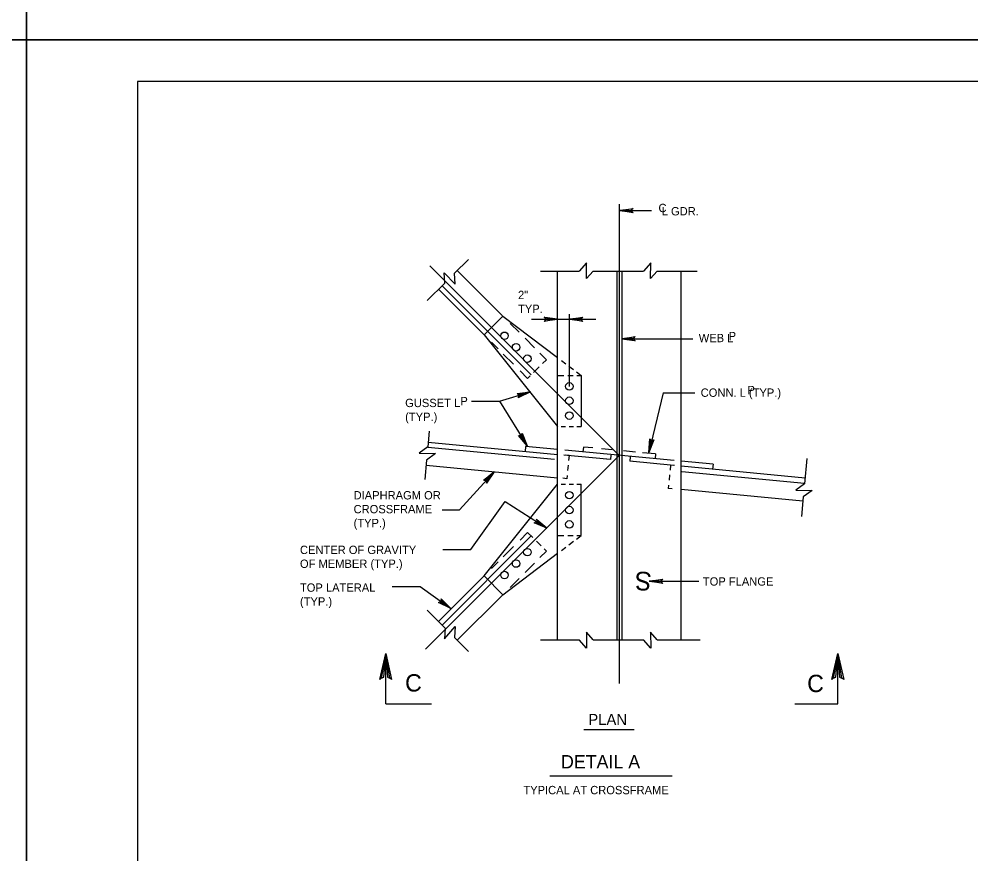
# Model space of a CAD drawing. Extents: x 30 to 2621, y -33 to 1155.
# Drawn here: x 868.8 to 1211.9, y 267.8 to 568.5 of the extents above; entities that cross this region are included whole.
import ezdxf

# ---------------------------------------------------------------- set-up
doc = ezdxf.new("R2010")
doc.units = 0
doc.layers.add('1', color=7, linetype='Continuous')
doc.layers.add('PLT-BNDY', color=7, linetype='Continuous')

msp = doc.modelspace()

# ---------------------------------------------------------------- linework, layer by layer
at = {"layer": '1'}
for p, q in [((911.5, 546), (911.5, -18)), ((1697.5, 546), (911.5, 546)), ((1085.19, 492.79), (1085.19, 501.85)), ((1085.27, 499.48), (1096.72, 499.48)), ((1085.19, 329.19), (1085.19, 492.79)), ((1025.81, 476.94), (1030.8, 481.93)), ((1016.93, 479.55), (1085.16, 411.31)), ((1026.79, 477.91), (1043.06, 461.64)), ((1056.82, 477.74), (1070.77, 477.74)), ((1062.9, 344.89), (1062.9, 477.74)), ((1075.75, 477.74), (1093.87, 477.74)), ((1084.24, 477.74), (1084.24, 344.89)), ((1086.07, 477.74), (1086.07, 344.89)), ((1098.85, 477.74), (1113.22, 477.74)), ((1107.42, 344.89), (1107.42, 477.74)), ((1015.95, 467.08), (1022.29, 473.41)), ((1020.03, 471.15), (1036.47, 454.71)), ((1021.32, 472.45), (1053.43, 440.34)), ((1036.47, 454.71), (1043.23, 461.47)), ((1043.23, 461.47), (1062.9, 446.58)), ((1053.54, 460.36), (1067.17, 460.36)), ((1067.17, 436.17), (1067.17, 462.24)), ((1067.17, 460.36), (1076.68, 460.36)), ((1045.83, 458.86), (1049.04, 455.66)), ((1036.47, 454.71), (1062.9, 421.7)), ((1051.19, 453.5), (1054.59, 450.11)), ((1086.07, 453.33), (1111.7, 453.33)), ((1039.07, 452.1), (1041.51, 449.67)), ((1043.35, 447.83), (1047.04, 444.13)), ((1056.56, 448.14), (1058.89, 445.8)), ((1054.31, 441.23), (1056.27, 443.18)), ((1057.48, 444.39), (1058.89, 445.8)), ((1064.29, 445.53), (1065.85, 444.34)), ((1066.97, 443.5), (1068.65, 442.23)), ((1049.39, 441.79), (1052.13, 439.04)), ((1052.13, 439.04), (1053.06, 439.98)), ((1062.9, 440.11), (1065.18, 440.11)), ((1066.61, 440.11), (1068.52, 440.11)), ((1069.69, 441.44), (1071.44, 440.11)), ((1069.87, 440.11), (1071.44, 440.11)), ((1071.44, 440.11), (1071.44, 421.7)), ((1042, 430.85), (1053.18, 434.2)), ((1100.96, 433.89), (1095.78, 412.42)), ((1100.96, 433.89), (1112.41, 433.89)), ((1031.9, 430.85), (1042, 430.85)), ((1042, 430.85), (1052.01, 414.76)), ((1016.69, 420.07), (1016.15, 414.39)), ((1064.17, 421.7), (1065.82, 421.7)), ((1067.06, 421.7), (1068.71, 421.7)), ((1069.87, 421.7), (1071.44, 421.7)), ((1016.3, 416.09), (1062.9, 411.65)), ((1016.13, 414.26), (1061.8, 409.92)), ((1051.37, 414.53), (1051.2, 412.77)), ((1062.9, 413.43), (1051.37, 414.53)), ((1104.95, 409.43), (1065.52, 413.18)), ((1072.26, 414.32), (1072.09, 412.56)), ((1075.62, 414), (1072.26, 414.32)), ((1082.64, 413.33), (1078.78, 413.7)), ((1091.04, 412.53), (1086.71, 412.94)), ((1098.23, 411.85), (1093.49, 412.3)), ((1098.23, 411.85), (1098.07, 410.08)), ((1015.7, 409.61), (1015.03, 402.58)), ((1015.37, 341.52), (1085.16, 411.31)), ((1082.03, 409.83), (1065.24, 411.43)), ((1067.05, 411.26), (1065.62, 411.39)), ((1067.05, 411.26), (1066.88, 409.45)), ((1082.03, 409.83), (1080.52, 409.97)), ((1082.18, 411.41), (1082.03, 409.83)), ((1089.07, 410.8), (1088.92, 409.18)), ((1104.86, 407.66), (1088.92, 409.18)), ((1090.1, 409.06), (1088.92, 409.18)), ((1118.95, 408.1), (1107.42, 409.19)), ((1152.82, 410.23), (1151.95, 401.13)), ((1015.51, 407.76), (1062.9, 403.25)), ((1027.6, 391.73), (1040.07, 405.39)), ((1066.72, 407.82), (1066.54, 405.92)), ((1103.63, 407.77), (1103.46, 405.97)), ((1105.06, 407.64), (1103.63, 407.77)), ((1152.11, 403.16), (1107.42, 407.41)), ((1107.73, 405.54), (1151.93, 401.33)), ((1118.95, 408.1), (1118.78, 406.33)), ((1066.26, 402.93), (1064.83, 403.06)), ((1066.37, 404.12), (1066.26, 402.93)), ((1103.3, 404.34), (1103.12, 402.44)), ((1036.47, 367.91), (1062.9, 400.92)), ((1064.17, 400.92), (1065.82, 400.92)), ((1067.06, 400.92), (1068.71, 400.92)), ((1069.87, 400.92), (1071.44, 400.92)), ((1071.44, 382.51), (1071.44, 400.92)), ((1102.95, 400.63), (1102.84, 399.45)), ((1104.27, 399.31), (1102.84, 399.45)), ((1151.32, 394.83), (1107.42, 399.01)), ((1031.7, 377.45), (1044.05, 394.69)), ((1044.05, 394.69), (1059.03, 385.09)), ((1151.5, 396.35), (1150.83, 389.32)), ((1021.37, 391.73), (1027.6, 391.73)), ((1021.32, 350.18), (1053.43, 382.29)), ((1049.39, 380.84), (1052.13, 383.58)), ((1052.13, 383.58), (1054, 381.71)), ((1062.9, 382.51), (1065.18, 382.51)), ((1066.61, 382.51), (1068.52, 382.51)), ((1069.69, 381.19), (1071.44, 382.51)), ((1069.87, 382.51), (1071.44, 382.51)), ((1021.6, 377.45), (1031.7, 377.45)), ((1043.35, 374.8), (1047.04, 378.49)), ((1055.3, 380.42), (1056.96, 378.75)), ((1058.09, 377.63), (1058.89, 376.82)), ((1064.29, 377.1), (1065.85, 378.28)), ((1066.97, 379.13), (1068.65, 380.4)), ((1043.23, 361.15), (1062.9, 376.04)), ((1056.56, 374.49), (1058.89, 376.82)), ((1039.07, 370.52), (1041.51, 372.96)), ((1051.19, 369.12), (1054.59, 372.52)), ((1020.03, 351.47), (1036.47, 367.91)), ((1036.47, 367.91), (1043.23, 361.15)), ((1003.34, 364.09), (1013.44, 364.09)), ((1013.44, 364.09), (1024.45, 356.18)), ((1045.83, 363.76), (1049.04, 366.97)), ((1095.97, 365.97), (1113.81, 365.97)), ((1026.79, 344.71), (1043.06, 360.99)), ((1015.95, 355.55), (1022.41, 349.08)), ((1025.81, 345.69), (1030.8, 340.7)), ((1056.82, 344.89), (1070.77, 344.89)), ((1075.75, 344.89), (1093.87, 344.89)), ((1098.85, 344.89), (1114.34, 344.89)), ((1000.98, 321.84), (1000.98, 339.93)), ((1163.9, 321.84), (1163.9, 339.93)), ((1000.98, 321.84), (1017.46, 321.84)), ((1148.46, 321.84), (1163.9, 321.84)), ((1072.45, 312.63), (1090.54, 312.63)), ((1060.09, 295.89), (1104.24, 295.89))]:
    msp.add_line(p, q, dxfattribs=at)
for points in [[(1089.89, 498.9), (1089.71, 499.23), (1085.27, 499.48), (1089.89, 498.9), (1090.12, 498.7), (1085.27, 499.48), (1089.71, 499.7), (1089.87, 500.03), (1085.27, 499.48), (1090.12, 500.25), (1089.87, 500.03)], [(1075.75, 477.74), (1073.33, 475), (1073.4, 480.7), (1070.77, 477.74)], [(1098.85, 477.74), (1096.43, 475), (1096.5, 480.7), (1093.87, 477.74)], [(1022.29, 473.41), (1022.06, 477.06), (1026.04, 472.98), (1025.81, 476.94)], [(1058.28, 460.94), (1058.46, 460.61), (1062.9, 460.36), (1058.28, 460.94), (1058.05, 461.14), (1062.9, 460.36), (1058.46, 460.14), (1058.3, 459.81), (1062.9, 460.36), (1058.05, 459.59), (1058.3, 459.81)], [(1071.78, 459.78), (1071.61, 460.12), (1067.17, 460.36), (1071.78, 459.78), (1072.02, 459.58), (1067.17, 460.36), (1071.61, 460.58), (1071.77, 460.91), (1067.17, 460.36), (1072.02, 461.13), (1071.77, 460.91)], [(1090.69, 452.76), (1090.52, 453.09), (1086.07, 453.33), (1090.69, 452.76), (1090.92, 452.55), (1086.07, 453.33), (1090.51, 453.55), (1090.67, 453.88), (1086.07, 453.33), (1090.92, 454.11), (1090.67, 453.88)], [(1048.6, 433.43), (1048.86, 433.16), (1053.18, 434.2), (1048.6, 433.43), (1048.31, 433.56), (1053.18, 434.2), (1048.99, 432.72), (1048.93, 432.36), (1053.18, 434.2), (1048.76, 432.07), (1048.93, 432.36)], [(1050.06, 418.99), (1049.87, 418.66), (1052.01, 414.76), (1050.06, 418.99), (1050.11, 419.29), (1052.01, 414.76), (1049.48, 418.42), (1049.11, 418.38), (1052.01, 414.76), (1048.79, 418.47), (1049.11, 418.38)], [(1097.43, 416.77), (1097.06, 416.68), (1095.78, 412.42), (1097.43, 416.77), (1097.68, 416.95), (1095.78, 412.42), (1096.61, 416.79), (1096.33, 417.02), (1095.78, 412.42), (1096.17, 417.32), (1096.33, 417.02)], [(1016.15, 414.39), (1012.99, 412.1), (1018.9, 411.96), (1015.7, 409.61)], [(1036.53, 402.38), (1036.9, 402.28), (1040.07, 405.39), (1036.53, 402.38), (1036.23, 402.34), (1040.07, 405.39), (1037.24, 401.97), (1037.38, 401.63), (1040.07, 405.39), (1037.37, 401.29), (1037.38, 401.63)], [(1151.95, 401.13), (1148.79, 398.84), (1154.7, 398.69), (1151.5, 396.35)], [(1055.46, 388.06), (1055.43, 387.69), (1059.03, 385.09), (1055.46, 388.06), (1055.37, 388.36), (1059.03, 385.09), (1055.18, 387.3), (1054.86, 387.11), (1059.03, 385.09), (1054.53, 387.06), (1054.86, 387.11)], [(1100.58, 365.39), (1100.41, 365.72), (1095.97, 365.97), (1100.58, 365.39), (1100.82, 365.19), (1095.97, 365.97), (1100.4, 366.19), (1100.57, 366.52), (1095.97, 365.97), (1100.82, 366.74), (1100.57, 366.52)], [(1021.04, 359.34), (1020.99, 358.97), (1024.45, 356.18), (1021.04, 359.34), (1020.97, 359.64), (1024.45, 356.18), (1020.72, 358.59), (1020.4, 358.42), (1024.45, 356.18), (1020.06, 358.38), (1020.4, 358.42)], [(1022.41, 349.08), (1022.17, 345.19), (1026.04, 349.65), (1025.81, 345.69)], [(1075.75, 344.89), (1073.33, 347.63), (1073.4, 341.92), (1070.77, 344.89)], [(1098.85, 344.89), (1096.43, 347.63), (1096.5, 341.92), (1093.87, 344.89)], [(999.38, 331.07), (1000.3, 331.4), (1000.98, 339.93), (999.38, 331.07), (998.82, 330.62), (1000.98, 339.93), (1001.58, 331.41), (1002.5, 331.09), (1000.98, 339.93), (1003.11, 330.62), (1002.5, 331.09)], [(1162.3, 331.07), (1163.23, 331.4), (1163.9, 339.93), (1162.3, 331.07), (1161.74, 330.62), (1163.9, 339.93), (1164.51, 331.41), (1165.43, 331.09), (1163.9, 339.93), (1166.04, 330.62), (1165.43, 331.09)]]:
    msp.add_lwpolyline(points, dxfattribs=at)
for centre in [(1043.8, 454.41), (1047.98, 450.27), (1052.05, 446.16), (1067.17, 436.17), (1067.17, 431.01), (1067.17, 425.65), (1067.17, 396.98), (1067.17, 391.62), (1067.17, 386.46), (1052.05, 376.47), (1047.98, 372.36), (1043.8, 368.21)]:
    msp.add_circle(centre, 1.35, dxfattribs=at)
at = {"layer": 'PLT-BNDY'}
for points in [[(30.5, 1155), (871.5, 1155), (871.5, 561), (30.5, 561)], [(871.5, 1155), (1712.5, 1155), (1712.5, 561), (871.5, 561)], [(30.5, 561), (871.5, 561), (871.5, -33), (30.5, -33)], [(871.5, 561), (1712.5, 561), (1712.5, -33), (871.5, -33)]]:
    msp.add_lwpolyline(points, close=True, dxfattribs=at)

# ---------------------------------------------------------------- texts
at = {"layer": '1'}
for s, height, p in [('C', 3, (1099.3, 498.94)), ('L GDR.', 3, (1100.47, 497.77)), ('2"', 3, (1048.68, 467.62)), ('TYP.', 3, (1048.68, 462.62)), ('WEB L', 3, (1113.81, 452.1)), ('P', 3, (1124.58, 452.8)), ('P', 3, (1131.37, 433.36)), ('P', 3, (1027.9, 429.38)), ('CONN. L (TYP.)', 3, (1114.51, 432.42)), ('GUSSET L', 3, (1008, 428.72)), ('(TYP.)', 3, (1008, 423.72)), ('DIAPHRAGM OR', 3, (989.41, 395.46)), ('CROSSFRAME', 3, (989.41, 390.46)), ('(TYP.)', 3, (989.41, 385.46)), ('CENTER OF GRAVITY', 3, (970.08, 375.79)), ('OF MEMBER (TYP.)', 3, (970.08, 370.79)), ('TOP FLANGE', 3, (1115.3, 364.41)), ('TOP LATERAL', 3, (970.08, 362.2)), ('(TYP.)', 3, (970.08, 357.2)), ('C', 6.24, (1007.97, 326.26)), ('C', 6.24, (1152.88, 326.05)), ('PLAN', 4, (1074, 314.19)), ('DETAIL A', 4.8, (1064.15, 298.57)), ('TYPICAL AT CROSSFRAME', 3, (1050.61, 289.26))]:
    msp.add_text(s, height=height, dxfattribs=at).set_placement(p)
msp.add_text('S', height=6.72, rotation=176.2424, dxfattribs=at).set_placement((1097.02, 369.19))

doc.saveas('drawing.dxf')
